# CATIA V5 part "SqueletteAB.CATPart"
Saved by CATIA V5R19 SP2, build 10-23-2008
Part number: SqueletteAB
Publications: "PointA", "AxeA", "LongueurB", "HauteurB", "PointB", "BodyAB"
Bounding box of the stored display mesh (mm): x -5.998 to 5.998, y -12 to 12, z -12 to 190
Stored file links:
  D:\France\IFMA\IAO\Projet\SqueletteAB.CATPart
  D:\France\IFMA\IAO\iao catia_Yang\squelette generale.CATPart
  D:\France\IFMA\IAO\Projet\pruangdaja_CAO.CATProduct
  D:\France\IFMA\IAO\Projet\SquelettePrin.CATPart
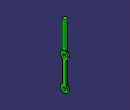
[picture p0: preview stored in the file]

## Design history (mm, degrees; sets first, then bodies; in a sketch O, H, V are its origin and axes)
Parameters
  LongueurB = 20 mm
  HauteurB = 150 mm
  Largeur = 10 mm
  RayonTrou = 5 mm {= Largeur /2}
External parameters (linked from other documents)
  External.LongueurAB = 180 mm
  External.Largeur = 10 mm
Set1
  Plane1: linked copy from another document
  Point1: linked copy from another document
Set2
  Point2: (0, 0, 180 {= External.LongueurAB}), relative to Point1
  Line1: type PtPt, FirstPoint Point1, SecondPoint Point2
  Point3: type OnCurve, Support Line1, Ratio 0.5
  Line2: type PtDir, RefPoint Point3, Direction (1, 0, 0), Start -20, End 20
  Circle1: type CtrRad, Start 0, End 180, Center Point3, Support Plane1, Radius 90 {= External.LongueurAB *Point3.Ratio}, FirstDirection (0, 1, 0)
  Sketch1 on Plane1, origin (0, 0, 0), H (0, 1, 0), V (0, 0, 1)
    reference projected point E1 (0, 180) from Point2
    arc A1 centre (0, 0) radius 12 from (-7.0588, 9.7043) to (7.0588, 9.7043) ccw
    line L1 (-5, 13.7477) -> (-5, 76.2523)
    line L2 (-5, 190) -> (5, 190)
    line L3 (5, 190) -> (5, 103.7477)
    point P1 (-5, 190)
    arc A2 centre (10, 13.7477) radius 5 from (7.0588, 9.7043) to (5, 13.7477) cw
    point P3 (5, 13.7477)
    arc A3 centre (-10, 13.7477) radius 5 from (-7.0588, 9.7043) to (-5, 13.7477) ccw
    circle A4 centre (0, 0) radius 5
    point P9 (5, 0)
    arc A5 centre (0, 90) radius 12 from (-7.0588, 99.7043) to (-7.0588, 80.2957) ccw
    arc A6 centre (10, 103.7477) radius 5 from (7.0588, 99.7043) to (5, 103.7477) cw
    line L4 (5, 13.7477) -> (5, 76.2523)
    arc A7 centre (10, 76.2523) radius 5 from (5, 76.2523) to (7.0588, 80.2957) cw
    point P13 (7.0588, 80.2957)
    line L5 (-5, 190) -> (-5, 103.7477)
    arc A8 centre (-10, 103.7477) radius 5 from (-7.0588, 99.7043) to (-5, 103.7477) ccw
    arc A9 centre (-10, 76.2523) radius 5 from (-5, 76.2523) to (-7.0588, 80.2957) ccw
    arc A10 centre (0, 90) radius 12 from (7.0588, 80.2957) to (7.0588, 99.7043) ccw
    circle A11 centre (0, 90) radius 5
    point P22 (5, 90)
    distance L1 L3 = 10 {= External.Largeur}
    distance L3 V = 5 {= External.Largeur /2}
    distance E1 L2 = 10
    radius A1 = 12 {= External.Largeur +2mm}
    radius A2 = 5
    radius A3 = 5
    radius A5 = 12 {= Sketch1.radius(A1)}
    radius A6 = 5
    radius A7 = 5
    radius A8 = 5
    radius A9 = 5
    horizontal: L2 H
    vertical: L1 V, L3 V
    tangency: A2 A1, A2 L3, A3 A1, A3 L1, A4 L3, A6 A5, A6 L3, L4 A2, A7 L4, A7 A5, L5 A3, A8 A5, A8 L5, A9 L1, A9 A5, A11 L3
    coincidence: A4 P9, P9 H, L3 P3, P1 L1, A5 P13, A5 A10, A11 P22, P22 L3
  Sketch2 on Plane1, origin (0, 0, 0), H (0, 1, 0), V (0, 0, 1)
    reference projected point E1 (0, 180) from Point2
    point P1 (0, 190)
    line L1 (0, 190) -> (-6, 190)
    line L2 (-6, 190) -> (-6, 105)
    line L3 (-6, 105) -> (0, 105)
    line L4 (0, 105) -> (0, 190)
    distance E1 L1 = 10
    length L3 = 6 {= External.Largeur /2+1mm}
    length L2 = 85
    coincidence: P1 V
    horizontal: L1 H, L3 H
    vertical: L2 V, L4 V
  Point4: (0, 0, 150 {= HauteurB}), relative to Point1
  Point5: (0, 20 {= LongueurB}, 0), relative to Point4
  Line3: type PtPt, FirstPoint Point4, SecondPoint Point5
Body1 (main body)
  Pad1: profile Sketch1, direction (1, 0, 0), length 2.5, opposite side length 2.5
  Shaft1: profile Sketch2, axis Sketch2.L4, angle 360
